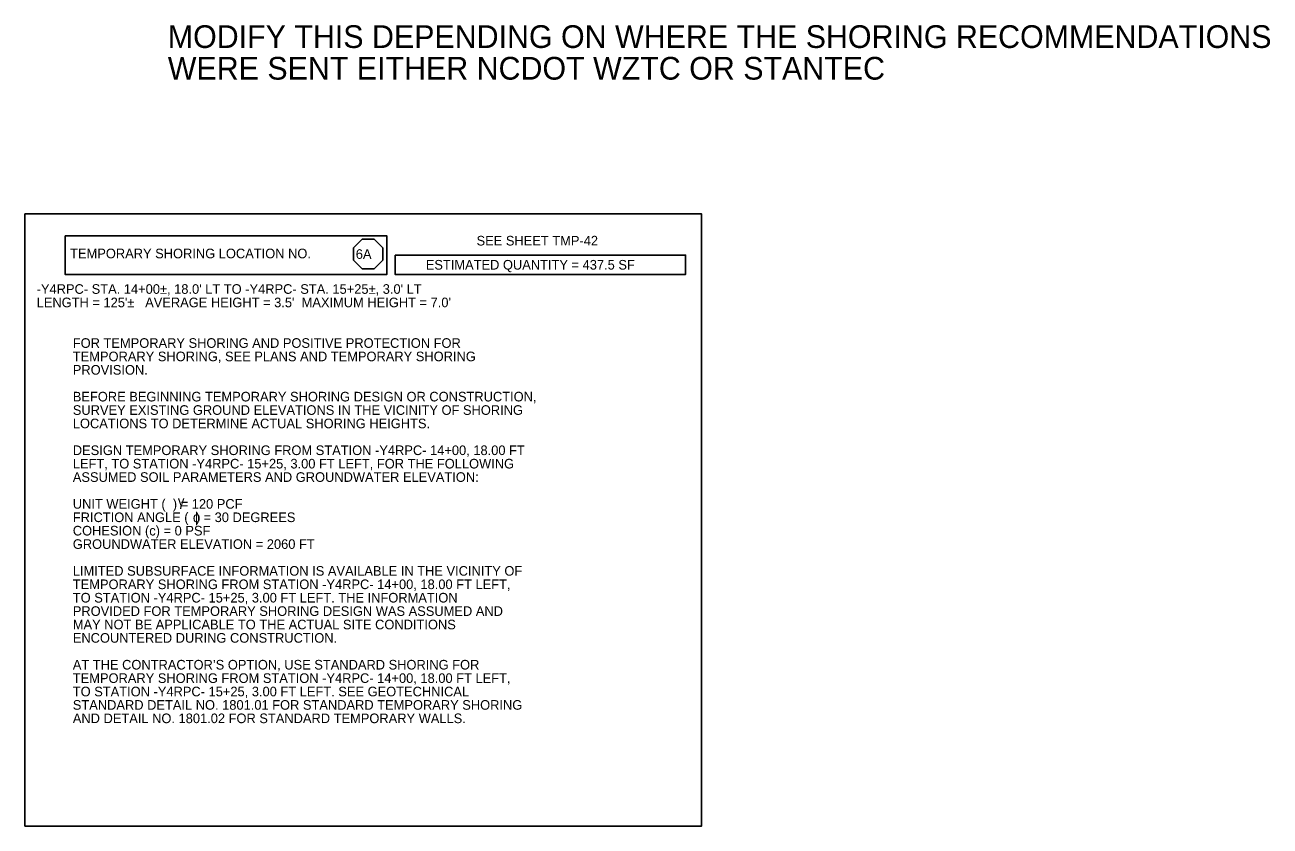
# Model space of a CAD drawing. Extents: x 2487012 to 2497594, y 369516 to 371986.
# Drawn here: x 2492595 to 2493478, y 369527 to 370095 of the extents above; entities that cross this region are included whole.
import ezdxf

# ---------------------------------------------------------------- set-up
doc = ezdxf.new("R2010")
doc.units = 0
for name, color, linetype in [('Scratch_Level_6', 7, 'Continuous'), ('TC LABEL TEMP SHORING', 7, 'Continuous'), ('TC SHEET BORDER LINE THIN', 7, 'Continuous'), ('TC SHEET TEXT', 7, 'Continuous')]:
    doc.layers.add(name, color=color, linetype=linetype)

msp = doc.modelspace()

# ---------------------------------------------------------------- linework, layer by layer
at = {"layer": 'TC LABEL TEMP SHORING'}
for p, q in [((2492834.25, 369942.72), (2492828.16, 369936.55)), ((2492828.16, 369936.55), (2492828.16, 369927.83)), ((2492842.85, 369942.72), (2492834.25, 369942.72)), ((2492848.94, 369936.55), (2492842.85, 369942.72)), ((2492848.94, 369927.83), (2492848.94, 369936.55)), ((2492828.16, 369927.83), (2492834.25, 369921.66)), ((2492842.85, 369921.66), (2492848.94, 369927.83)), ((2492834.25, 369921.66), (2492842.85, 369921.66))]:
    msp.add_line(p, q, dxfattribs=at)
at = {"layer": 'TC SHEET BORDER LINE THIN'}
for points in [[(2492595.29, 369960.68), (2493074.73, 369960.68), (2493074.73, 369527.04), (2492595.29, 369527.04)], [(2492623.77, 369945.09), (2492851.83, 369945.09), (2492851.83, 369917.83), (2492623.77, 369917.83)], [(2492857.59, 369931.46), (2493063.37, 369931.46), (2493063.37, 369917.83), (2492857.59, 369917.83)]]:
    msp.add_lwpolyline(points, close=True, dxfattribs=at)

# ---------------------------------------------------------------- texts
at = {"layer": 'Scratch_Level_6'}
for s, p in [('MODIFY THIS DEPENDING ON WHERE THE SHORING RECOMMENDATIONS ', (2492696.53, 370078.21)), ('WERE SENT EITHER NCDOT WZTC OR STANTEC', (2492696.53, 370055.78))]:
    msp.add_text(s, height=16.0939, dxfattribs=at).set_placement(p)
at = {"layer": 'TC LABEL TEMP SHORING'}
for s, height, p in [('6A', 6.814, (2492829.73, 369928.83)), ('γ', 7.2, (2492703.58, 369753.79)), ('    ɸ', 7.2, (2492703.58, 369742.27))]:
    msp.add_text(s, height=height, dxfattribs=at).set_placement(p)
at = {"layer": 'TC SHEET BORDER LINE THIN'}
for s, height, p in [('FOR TEMPORARY SHORING AND POSITIVE PROTECTION FOR', 6.8137, (2492629.23, 369865.8)), ('TEMPORARY SHORING, SEE PLANS AND TEMPORARY SHORING', 6.8137, (2492629.23, 369856.31)), ('PROVISION.', 6.814, (2492629.23, 369846.81)), ('BEFORE BEGINNING TEMPORARY SHORING DESIGN OR CONSTRUCTION,', 6.8137, (2492629.23, 369827.83)), ('SURVEY EXISTING GROUND ELEVATIONS IN THE VICINITY OF SHORING', 6.8137, (2492629.23, 369818.33)), ('LOCATIONS TO DETERMINE ACTUAL SHORING HEIGHTS.', 6.8137, (2492629.23, 369808.84)), ('DESIGN TEMPORARY SHORING FROM STATION -Y4RPC- 14+00, 18.00 FT', 6.8137, (2492629.23, 369789.85)), ('LEFT, TO STATION -Y4RPC- 15+25, 3.00 FT LEFT, FOR THE FOLLOWING', 6.8137, (2492629.23, 369780.35)), ('ASSUMED SOIL PARAMETERS AND GROUNDWATER ELEVATION:', 6.8137, (2492629.23, 369770.86)), ('UNIT WEIGHT (  ) = 120 PCF', 6.8137, (2492629.23, 369751.87)), ('FRICTION ANGLE (  ) = 30 DEGREES', 6.8137, (2492629.23, 369742.38)), ('COHESION (c) = 0 PSF', 6.8137, (2492629.23, 369732.88)), ('GROUNDWATER ELEVATION = 2060 FT', 6.8137, (2492629.23, 369723.39)), ('LIMITED SUBSURFACE INFORMATION IS AVAILABLE IN THE VICINITY OF', 6.8137, (2492629.23, 369704.4)), ('TEMPORARY SHORING FROM STATION -Y4RPC- 14+00, 18.00 FT LEFT,', 6.8137, (2492629.23, 369694.9)), ('TO STATION -Y4RPC- 15+25, 3.00 FT LEFT. THE INFORMATION', 6.8137, (2492629.23, 369685.41)), ('PROVIDED FOR TEMPORARY SHORING DESIGN WAS ASSUMED AND', 6.8137, (2492629.23, 369675.92)), ('MAY NOT BE APPLICABLE TO THE ACTUAL SITE CONDITIONS', 6.8137, (2492629.23, 369666.42)), ('ENCOUNTERED DURING CONSTRUCTION.', 6.8137, (2492629.23, 369656.93)), ('AT THE CONTRACTOR’S OPTION, USE STANDARD SHORING FOR', 6.8137, (2492629.23, 369637.94)), ('TEMPORARY SHORING FROM STATION -Y4RPC- 14+00, 18.00 FT LEFT,', 6.8137, (2492629.23, 369628.44)), ('TO STATION -Y4RPC- 15+25, 3.00 FT LEFT. SEE GEOTECHNICAL', 6.8137, (2492629.23, 369618.95)), ('STANDARD DETAIL NO. 1801.01 FOR STANDARD TEMPORARY SHORING', 6.8137, (2492629.23, 369609.46)), ('AND DETAIL NO. 1801.02 FOR STANDARD TEMPORARY WALLS.', 6.8137, (2492629.23, 369599.96))]:
    msp.add_text(s, height=height, dxfattribs=at).set_placement(p)
at = {"layer": 'TC SHEET TEXT'}
for s, p in [('SEE SHEET TMP-42', (2492915.28, 369938.3)), ('TEMPORARY SHORING LOCATION NO.', (2492627.34, 369929.23)), ('ESTIMATED QUANTITY = 437.5 SF', (2492879.31, 369921.24)), ("-Y4RPC- STA. 14+00±, 18.0' LT TO -Y4RPC- STA. 15+25±, 3.0' LT", (2492603.62, 369904.06)), ("LENGTH = 125'±   AVERAGE HEIGHT = 3.5'  MAXIMUM HEIGHT = 7.0'", (2492603.62, 369894.56))]:
    msp.add_text(s, height=6.8137, dxfattribs=at).set_placement(p)

doc.saveas('drawing.dxf')
